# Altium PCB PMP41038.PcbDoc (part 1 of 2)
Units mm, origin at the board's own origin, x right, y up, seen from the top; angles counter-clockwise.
Board outline 101.5 x 48.5 mm, 4 copper layers (Top Layer, Signal Layer 1, Signal Layer 2, Bottom Layer), stack 0.713 mm thick; 126 components, 51 nets, 261 pads, 192 vias.
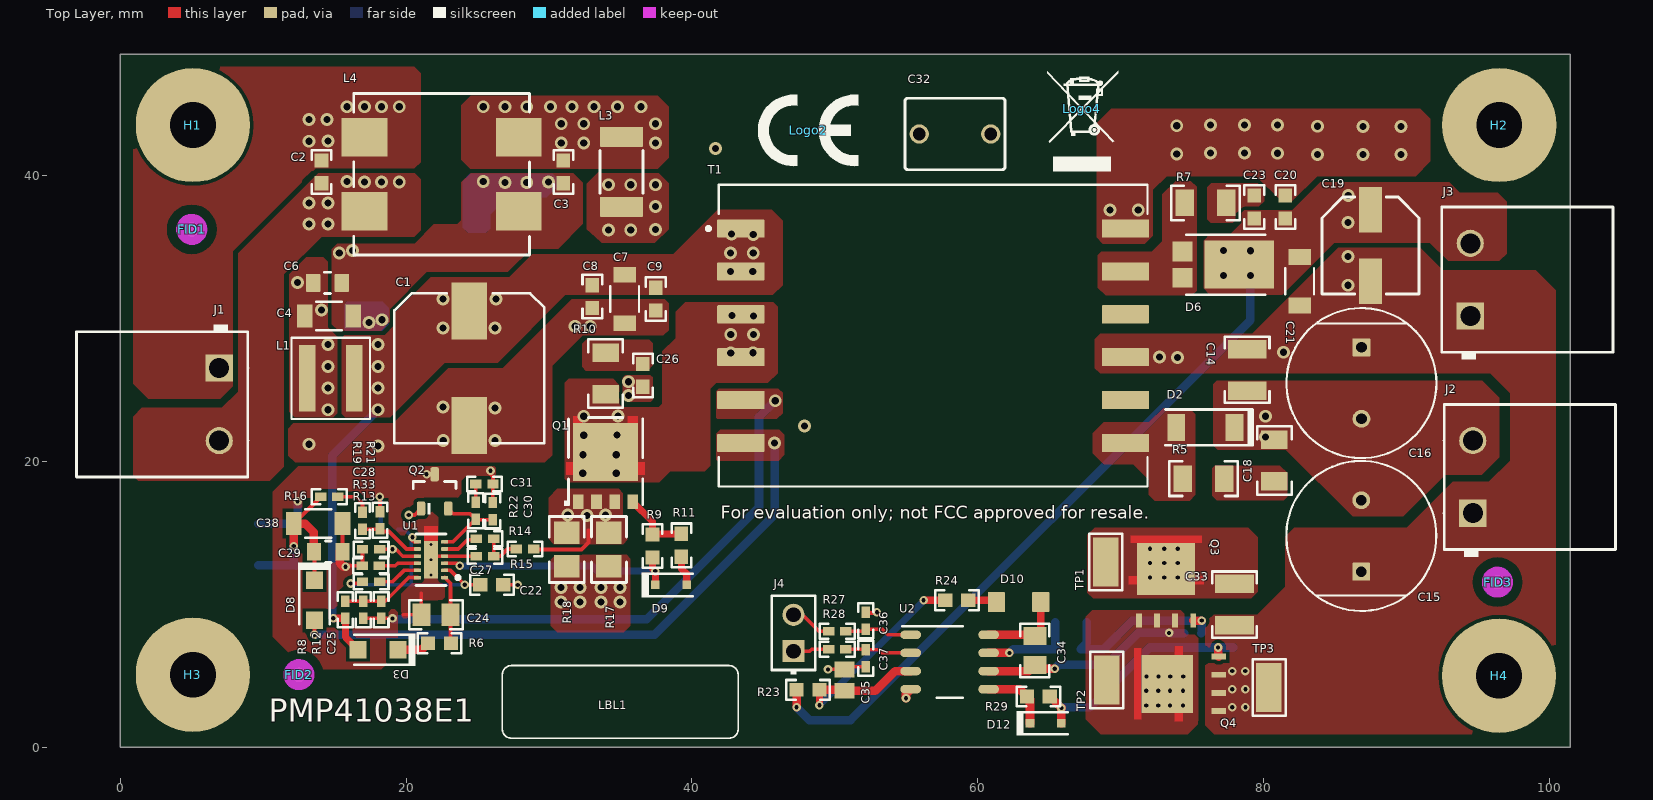
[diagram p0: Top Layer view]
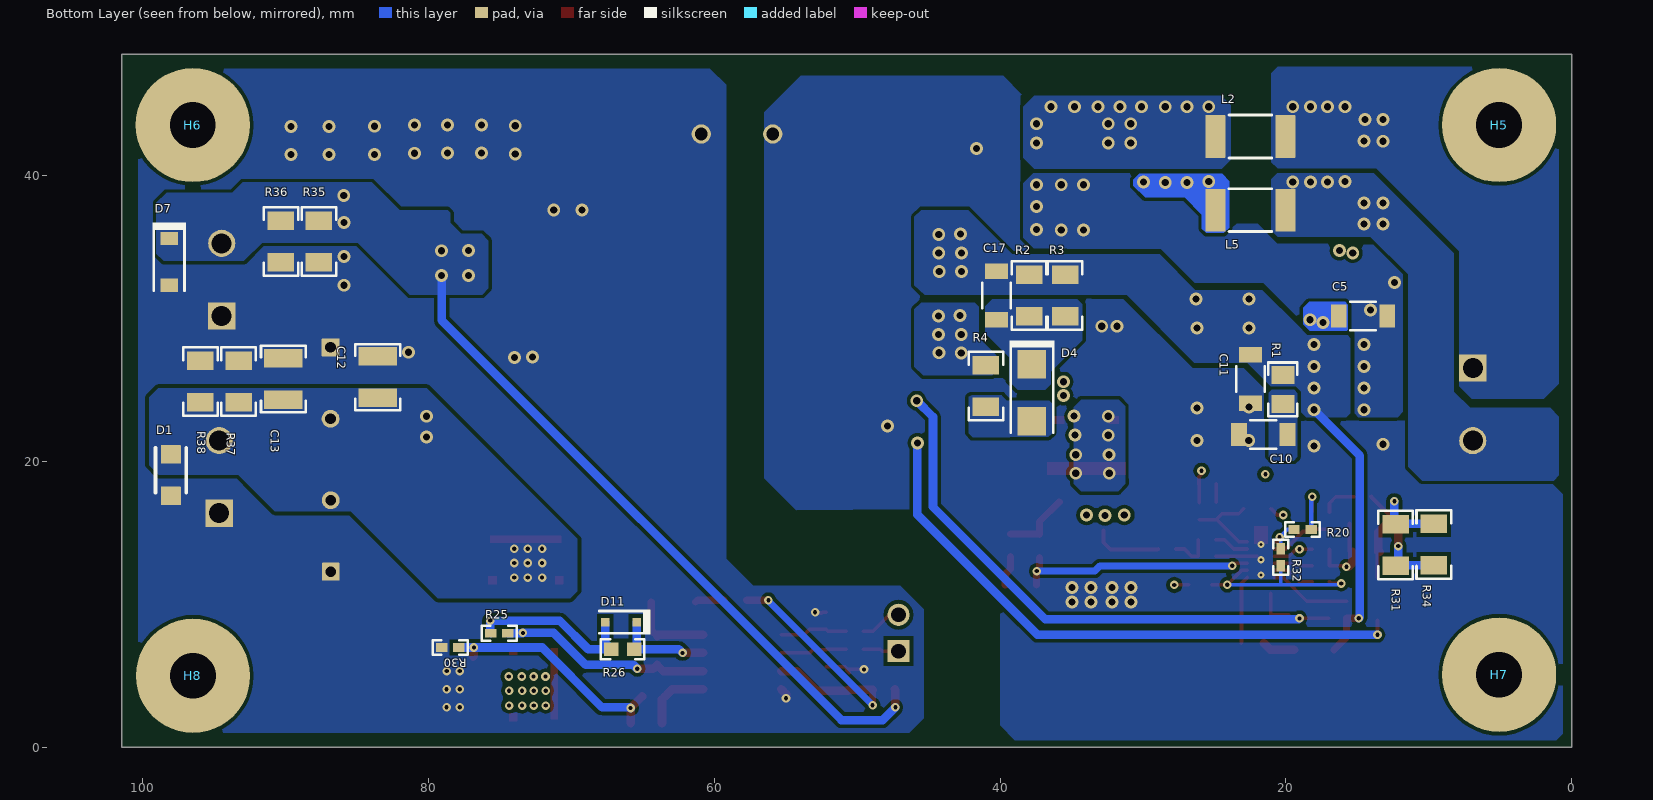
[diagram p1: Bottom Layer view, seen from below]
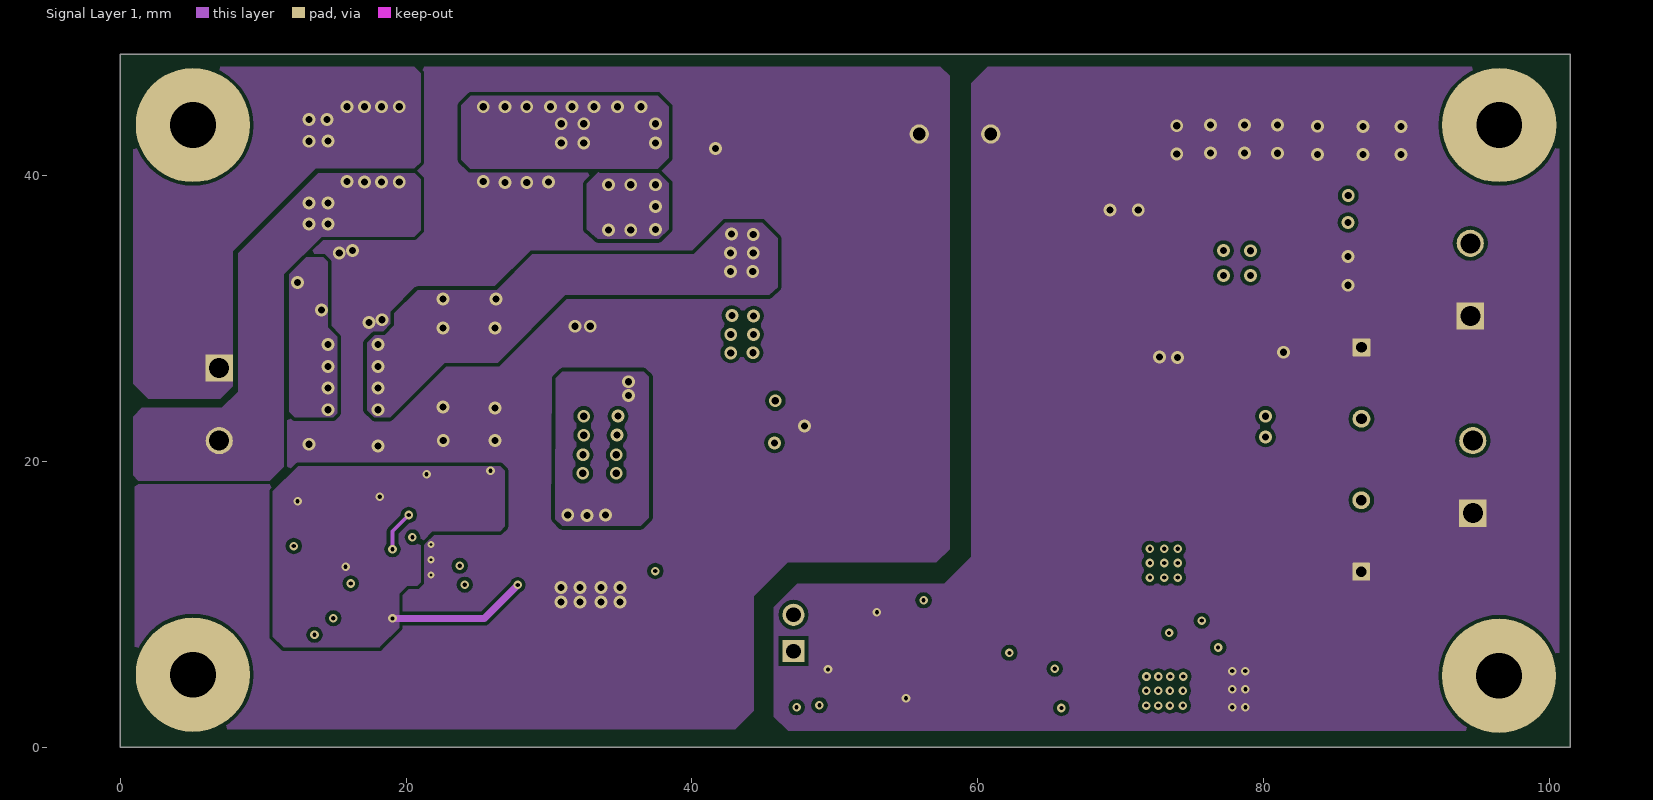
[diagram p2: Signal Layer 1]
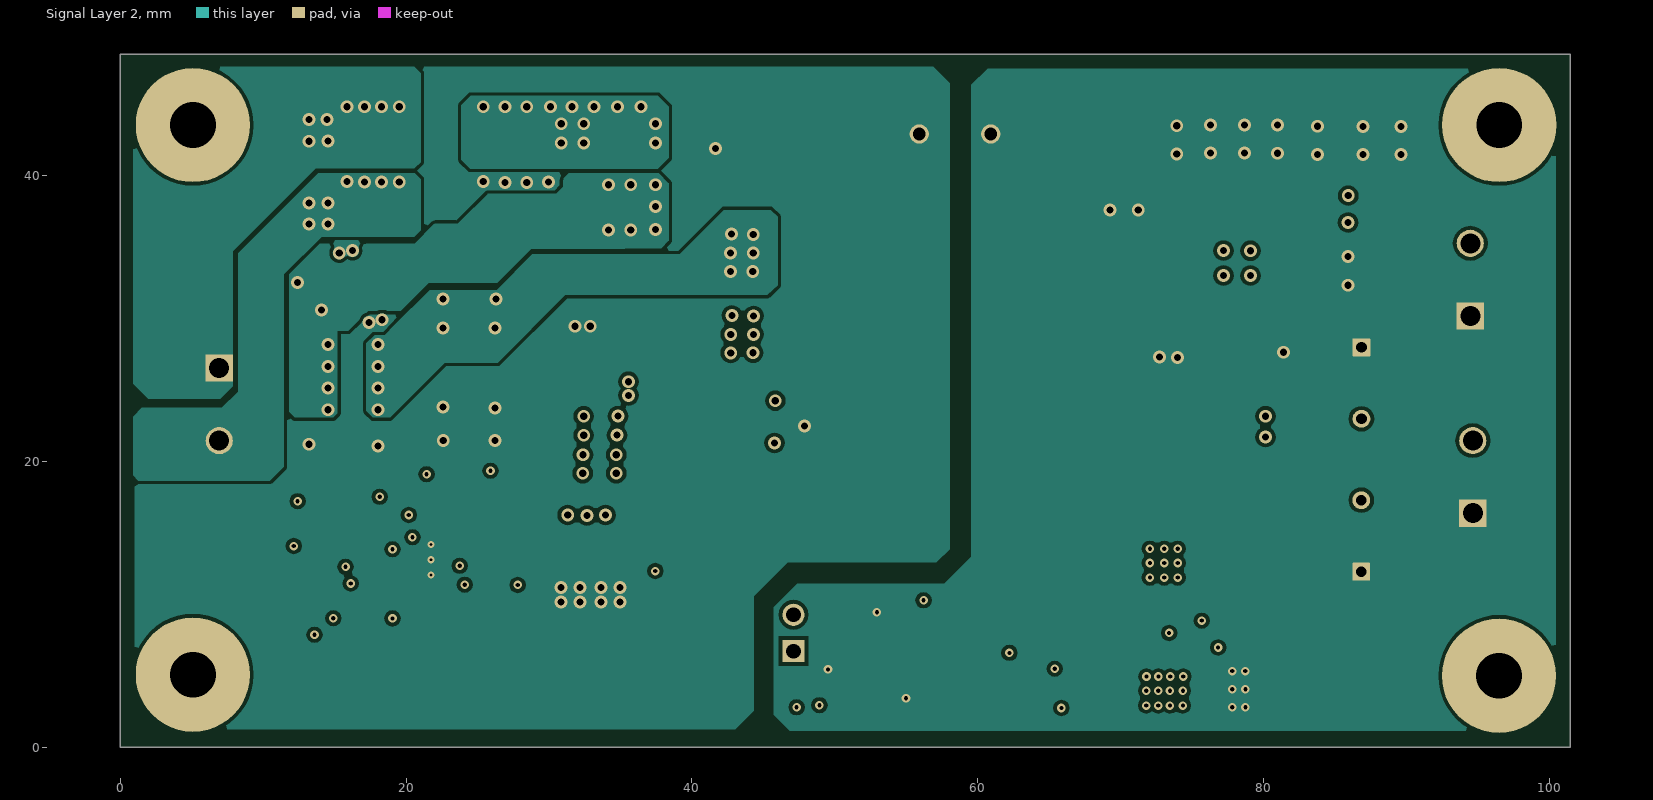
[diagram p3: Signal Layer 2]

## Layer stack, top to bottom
Top Solder: solder mask 0.0102, Solder Resist, Dk 3.5
Top Layer: signal copper 0.0356
Dielectric1: dielectric 0.19, Dk 4.2
Signal Layer 1: signal copper 0.036
Dielectric 4: dielectric 0.19, Dk 4.2
Signal Layer 2: signal copper 0.036
Dielectric 7: dielectric 0.19, Dk 4.2
Bottom Layer: signal copper 0.0356
Bottom Solder: solder mask 0.0102, Solder Resist, Dk 3.5

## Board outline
0,0 0,48.5 101.5,48.5 101.5,0

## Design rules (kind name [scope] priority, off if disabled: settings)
AcuteAngle [All] p1: minimum=4.50000000000000E+0001 checktracksonly=FALSE
AssemblyTestPointUsage [All] p1: valid=2
Clearance Clearance_BoardEdge_MountingHoles [OnCopper and InComponentClass('Mounting Holes') vs IsKeepOut] p1: gap=1.016 ignorepadtopadclearanceinfootprint=FALSE except(0: Arc-Hole Track-Hole SMDPad-Hole THPad-Hole Via-Hole Fill-Hole Poly-Hole Region-Hole Text-Hole)
Clearance Clearance_BoardEdge_Poly [OnCopper and InPoly vs IsKeepOut] p2: gap=0.635 ignorepadtopadclearanceinfootprint=FALSE except(0: Arc-Hole Track-Hole SMDPad-Hole THPad-Hole Via-Hole Fill-Hole Poly-Hole Region-Hole Text-Hole)
Clearance Clearance_BoardEdge [OnCopper and Not InComponentClass('Logo') and not InComponentClass('FiducialMark') and not InRegion(1000,500,4000,800) and Not IsKeepout vs IsKeepOut] p3: gap=0.127 ignorepadtopadclearanceinfootprint=FALSE except(0: Arc-Hole Track-Hole SMDPad-Hole THPad-Hole Via-Hole Fill-Hole Poly-Hole Region-Hole Text-Hole)
Clearance Clearance_Poly [InPolygon] p4: gap=0.254 ignorepadtopadclearanceinfootprint=FALSE except(0: Arc-Hole Track-Hole SMDPad-Hole THPad-Hole Via-Hole Fill-Hole Poly-Hole Region-Hole Text-Hole)
Clearance [All] p5: gap=0.203 ignorepadtopadclearanceinfootprint=FALSE except(0: Arc-Hole Track-Hole SMDPad-Hole THPad-Hole Via-Hole Fill-Hole Poly-Hole Region-Hole Text-Hole)
ComponentClearance ComponentClearance_Logo [All] p1: gap=0.254 collisioncheckmode=3 verticalgap=0.254 showdistances=TRUE
ComponentClearance ComponentClearance_ScrewToNut [(HasFootprint('NY PMS 440 0025 PH')) vs (HasFootprint('Keystone_1902C'))] p2: gap=0.127 collisioncheckmode=3 verticalgap=0.254 showdistances=FALSE
ComponentClearance ComponentClearance_MountingHoles [InComponentClass('Mounting Holes')] p3: gap=0.254 collisioncheckmode=3 verticalgap=2540 showdistances=FALSE
ComponentClearance ComponentClearance_SmallPassives [HasFootprint('0201*') or HasFootprint('0402*') or HasFootprint('0508') or HasFootprint('0603*') or HasFootprint('0612') or HasFootprint('0805*') or HasFootprint('0815*') or HasFootprint('0830*') or HasFootprint('1206*') or HasFootprint('1210*') or HasFootprint('1808*') or HasFootprint('1812*') or HasFootprint('1825*') or HasFootprint('2010*') or HasFootprint('2220*') or HasFootprint('2225*') or HasFootprint('2512*') or HasFootprint('2728*') or HasFootprint('3518*') vs HasFootprint('0201*') or HasFootprint('0402*') or HasFootprint('0508') or HasFootprint('0603*') or HasFootprint('0612') or HasFootprint('0805*') or HasFootprint('0815*') or HasFootprint('0830*') or HasFootprint('1206*') or HasFootprint('1210*') or HasFootprint('1808*') or HasFootprint('1812*') or HasFootprint('1825*') or HasFootprint('2010*') or HasFootprint('2220*') or HasFootprint('2225*') or HasFootprint('2512*') or HasFootprint('2728*') or HasFootprint('3518*')] p4: gap=0.254 collisioncheckmode=3 verticalgap=0.254 showdistances=FALSE
ComponentClearance ComponentClearance_THtoSMT [IsThruComponent vs IsSMTComponent] p5: gap=0.254 collisioncheckmode=3 verticalgap=2540 showdistances=FALSE
ComponentClearance ComponentClearance_THtoTH [IsThruComponent vs IsThruComponent] p6: gap=0.254 collisioncheckmode=3 verticalgap=2540 showdistances=FALSE
ComponentClearance [All] p7: gap=0.254 collisioncheckmode=3 verticalgap=0.254 showdistances=FALSE
DiffPairsRouting [All] p1: maxlimit=2.54 minlimit=0.254 mostfreqgap=0.254 toplayer_minwidth=0.381 toplayer_maxwidth=0.381 toplayer_prefwidth=0.381 midlayer1_minwidth=0.381 midlayer1_maxwidth=0.381 midlayer1_prefwidth=0.381 midlayer6_minwidth=0.381 midlayer6_maxwidth=0.381 midlayer6_prefwidth=0.381 bottomlayer_minwidth=0.381 bottomlayer_maxwidth=0.381 bottomlayer_prefwidth=0.381 maxuncoupledlength=25.4
FabricationTestPointUsage TestPointUsage [All] p1: valid=2 allowmultiple=FALSE
FabricationTestpoint Testpoint [All] p1: side=3 testpointundercomponent=TRUE minsize=1.016 maxsize=2.54 preferedsize=1.524 minholesize=0 maxholesize=1.016 preferedholesize=0.813 testpointgrid=0.025 allowsidetop=TRUE allowsidebottom=TRUE usegrid=TRUE gridtolerance=0
FanoutControl Fanout_LCC [IsLCC] p1: bgadir=Out bgaviamode=Centered fanoutstyle=Auto fanoutdirection=Alternating viagrid=0.025 // Fanout_LCC (Default Rule)
FanoutControl Fanout_BGA [IsBGA] p2: bgadir=Out bgaviamode=Centered fanoutstyle=Auto fanoutdirection=Alternating viagrid=0.025 // Fanout_BGA (Default Rule)
FanoutControl Fanout_Default [All] p4: bgadir=Out bgaviamode=Centered fanoutstyle=Auto fanoutdirection=Alternating viagrid=0.025 // Fanout_Default (Default Rule)
FanoutControl Fanout_Small [(CompPinCount < 5)] p5: bgadir=Out bgaviamode=Centered fanoutstyle=Auto fanoutdirection=OutThenIn viagrid=0.025 // Fanout_Small (Default Rule)
HoleSize [All] p1: absolutevalues=TRUE maxlimit=6.375 minlimit=0.152 maxpercent=80.000 minpercent=20.000
MinimumAnnularRing [All] p1: minimumring=0.076
MinimumSolderMaskSliver MinimumSolderMaskSliver_Logo [InComponentClass('Logo') vs InComponentClass('Logo')] p1: minsoldermaskwidth=0.018
MinimumSolderMaskSliver [All] p2: minsoldermaskwidth=0
PlaneConnect [All] p1: planeconnectstyle=Direct reliefexpansion=0.254 reliefentries=4 reliefconductorwidth=0.254 reliefairgap=0.254
PolygonConnect [All] p1: connectstyle=Direct reliefconductorwidth=0.254 reliefentries=4 polygonreliefangle="90 Angle" airgapwidth=0.254
RoutingCorners [All] p1: cornerstyle=45-Degree minsetback=0.254 maxsetback=2.54
RoutingLayers [All] p1: top layer_v5=TRUE mid layer 1_v5=TRUE mid layer 6_v5=FALSE bottom layer_v5=TRUE
RoutingVias [All] p1: holewidth=0.406 width=0.864 viastyle="Through Hole" minholewidth=0.203 minwidth=0.406 maxholewidth=1.016 maxwidth=1.651
SMDToCorner [All] p1: distance=0
SilkToBoardRegionClearance [Not ((IsComment or IsDesignator) And (Hide <> 'False')) and not InRegion(1000,500,4000,800)] p1:
SilkToSilkClearance [All] p1: silktosilkclearance=0
SilkToSolderMaskClearance SilkscreenOverComponentPads [IsPad] p1: minsilkscreentomaskgap=0 clearancetoexposedcopper=TRUE
SolderMaskExpansion [All] p1: expansion=0.076
Width [All] p1: maxlimit=2.54 minlimit=0.152 preferedwidth=0.254 checkconnectedcopper=TRUE
13 further rules are at their usual default settings.

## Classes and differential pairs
component class Header: J4
component class "PMP41038 Driver": C33 C34 C35 C36 C37 D10 D11 D12 J4 Q3 Q4 R23 R24 R25 R26 R27 R28 R29 R30 TP1 TP2 TP3 U2
component class "PMP41038 PowerSupply": C1 C2 C3 C4 C5 C6 C7 C8 C9 C10 C11 C12 C13 C14 C15 C16 C17 C18 C19 C20 C21 C22 C23 C24 C25 C26 C27 C28 C29 C30 C31 C32 C38 D1 D2 D3 D4 D6 D7 D8 D9 J1 J2 J3 L1 L2 L3 L4 L5 NT1 Q1 Q2 R1 R2 R3 R4 R5 R6 R7 R8 R9 R10 R11 R12 R13 R14 R15 R16 R17 R18 R19 R20 R21 R22 R31 R32 R33 R34 R35 R36 R37 R38 T1 U1
component class "Mounting Holes": H1 H2 H3 H4
component class Logo: Logo1
component class PMP41038_Hardware: FID1 FID2 FID3 H1 H2 H3 H4 H5 H6 H7 H8 LBL1 Logo1 Logo2 Logo3 Logo4 ZZ1 ZZ2 ZZ3 ZZ4
component class FiducialMark: FID1 FID2 FID3
component class AssemblyNote: ZZ1 ZZ2 ZZ3 ZZ4
component class Label: LBL1

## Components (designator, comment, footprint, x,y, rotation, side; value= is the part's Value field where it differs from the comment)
C1 "EEHZA1H101P" SM_RADIAL_10BMM 24.431,26.524 r270 top value=100uF
C2 "CGA3E2X7R1H104K080AA" 0603 14.082,40.275 r270 top value=0.1uF
C3 "CGA3E2X7R1H104K080AA" 0603 31.012,40.275 r270 top value=0.1uF
C4 "CGA5L1X7R1H106K160AC" 1206_190 14.606,30.188 r0 top value=10uF
C5 "CGA5L1X7R1H106K160AC" 1206_190 14.606,30.188 r0 bottom value=10uF
C6 "CGA4J3X7R1H105K125AB" 0805_HV1 14.5,32.503 r0 top value=1uF
C7 "CGA5L1X7R1H106K160AC" 1206_190 35.306,31.374 r270 top value=10uF
C8 "CGA3E2X7R1H104K080AA" 0603 33.041,31.545 r270 top value=0.1uF
C9 "CGA3E2X7R1H104K080AA" 0603 37.48,31.371 r270 top value=0.1uF
C10 "CGA5L1X7R1H106K160AC" 1206_190 21.59,21.897 r0 bottom value=10uF
C11 "CGA5L1X7R1H106K160AC" 1206_190 22.479,25.781 r270 bottom value=10uF
C12 "GRM32DR72E224KW01L" 1210_220 83.566,25.908 r270 bottom value=0.22uF
C13 "GRM32DR72E224KW01L" 1210_220 90.17,25.781 r270 bottom value=0.22uF
C14 "GRM32DR72E224KW01L" 1210_220 78.867,26.416 r270 top value=0.22uF
C15 "UVK2D220MPD" FP-UVK2D220MPD_RADIAL-MFG 86.859,14.792 r90 top value=22µF
C16 "UVK2D220MPD" FP-UVK2D220MPD_RADIAL-MFG 86.868,25.49 r270 top value=22µF
C17 "CGA5L2X7R2A104K160AA" 1206_180 40.259,31.623 r270 bottom value=0.1uF
C18 "GRM31A5C2J101JW01D" 1206 80.772,20.066 r270 top value=100pF
C19 "EEH-ZA1E101XP" Panasonic_D8 87.503,35.114 r270 top value=100uF
C20 "CGA3E2X7R1H104K080AA" 0603 81.55,37.813 r270 top value=0.1uF
C21 "CGA5L1X7R1E106K160AE" 1206_190 82.55,32.614 r270 top value=10uF
C22 "GCM188R71E105KA64D" 0603 26,11.379 r0 top value=1uF
C23 "GRM1885C2A681JA01D" 0603 79.375,37.813 r90 top value=680pF
C24 "CGA4J3X7R1H105K125AB" 0805_HV 22.09,9.279 r180 top value=1uF
C25 "CGA2B2X7R1H221K050BA" 0402 18.25,9.629 r270 top value=220pF
C26 "GCM1885C2A102JA16D" 0603 36.576,26.03 r270 top value=1000pF
C27 "GCM155R71H102KA37D" 0402 25.525,13.379 r180 top value=1000pF
C28 "GCM155R71C104JA55D" 0402 17.55,13.859 r180 top value=0.1uF
C29 "CGA4J3X7R1H105K125AB" 0805_HV1 14.55,13.684 r0 top value=1uF
C30 "GCM155R71H102KA37D" 0402 26.075,16.532 r90 top value=1000pF
C31 "CGA2B3X7R1H683K050BB" 0402 25.486,18.429 r0 top value=0.068uF
C32 "CS95ZU2GA332MAGKA" CK45-RR_700x500x1100 58.42,42.926 r180 top value=3300pF
C33 "GRM32DR72E224KW01L" 1210_220 77.983,9.988 r270 top value=0.22uF
C34 "GCM21BR71H474KA55L" 0805_HV 64.016,6.773 r270 top value=0.47uF
C35 "CGA4J1X7R1E475K125AC" 0805L 50.673,4.699 r90 top value=4.7uF
C36 "CGA2B2C0G1H101J050BA" 0402 52.184,8.848 r90 top value=100pF
C37 "CGA2B2C0G1H101J050BA" 0402 52.184,6.223 r270 top value=100pF
C38 "CGA5L1X7R1H106K160AC" 1206_190 13.848,15.658 r0 top value=10uF
D1 "BZD27C200P-E3-08" DO-219AB 98.044,19.05 r270 bottom value=200V
D2 "ES1JAF" SMAF 75.946,22.393 r180 top value=600V
D3 "PMEG10010ELRX" SOD-123W 18.034,6.823 r180 top value=100V
D4 "ES1D-E3/61T" SMA 37.786,24.822 r270 bottom value=200V
D6 "PDS3100Q-13" POWERDI5 76.327,33.782 r0 top value=100V
D7 "BZT52C18-7-F" SOD-123 98.171,33.974 r270 bottom value=18V
D8 "PMEG10010ELRX" SOD-123W 13.589,10.287 r270 top value=100V
D9 "BAT54WSQ-7-F" SOD-323 38.549,11.361 r0 top value=30V
D10 "US1DFA" SOD-123FA 62.873,10.16 r180 top value=200V
D11 "BAT54WSQ-7-F" SOD-323 66.548,8.763 r0 bottom value=30V
D12 "BAT54WSQ-7-F" SOD-323 64.77,1.691 r0 top value=30V
FID1 "Fiducial" Fiducial10-20 5,36.25 r0 top
FID2 "Fiducial" Fiducial10-20 12.5,5.08 r0 top
FID3 "Fiducial" Fiducial10-20 96.393,11.557 r0 top
H1 "NY PMS 440 0025 PH" "NY PMS 440 0025 PH" 5.08,43.55 r0 top
H2 "NY PMS 440 0025 PH" "NY PMS 440 0025 PH" 96.513,43.55 r0 top
H3 "NY PMS 440 0025 PH" "NY PMS 440 0025 PH" 5.08,5.08 r0 top locked
H4 "NY PMS 440 0025 PH" "NY PMS 440 0025 PH" 96.5,5 r0 top
H5 "1902C" Keystone_1902C 5.08,43.55 r180 bottom
H6 "1902C" Keystone_1902C 96.513,43.55 r180 bottom
H7 "1902C" Keystone_1902C 5.08,5.08 r180 bottom locked
H8 "1902C" Keystone_1902C 96.5,5 r180 bottom
J1 "1759017" Phoenix_1759017 6.923,24 r270 top
J2 "1759017" Phoenix_1759017 94.661,18.923 r90 top
J3 "1759017" Phoenix_1759017 94.488,32.733 r90 top
J4 "PEC01DAAN" Sullins_PxC01DAAN 47.117,8.001 r90 top
L1 "XAL5030-472MEB" XAL5030 14.732,25.815 r0 top value=4.7uH
L2 "74279226101" 1812_170_HighSpeed 22.49,42.75 r0 bottom value="100 ohm"
L3 "74279226101" 1812_170_HighSpeed 35.075,40.277 r270 top value="100 ohm"
L4 "ACM1211-701-2PL-TL01" TDK_ACM1211 22.49,40.108 r90 top
L5 "74279226101" 1812_170_HighSpeed 22.49,37.592 r0 bottom value="100 ohm"
LBL1 "THT-14-423-10" Label_650x200 34.991,3.175 r0 top
Logo1 "Texas Instruments" TI_Stacked_Overlay_Small 126.619,17.526 r0 top
Logo2 "CE Mark" CE_Mark_5mm 48.133,43.18 r0 top
Logo3 "FCC disclaimer" FCC_disclaimer 59.69,65.852 r0 top
Logo4 "WEEE logo" WEEE_Minimum 67.31,44.698 r0 top
Q1 "NVMFS5C670NLWFAFT1G" SO-8FL 33.962,19.973 r90 top value=60V
Q2 "MMBT3906" SOT-23 22,17.907 r90 top value="40 V"
Q3 "SQJ454EP-T1_GE3" PowerPAK_SO-8L 73.197,11.685 r90 top value=200V
Q4 "SQJ454EP-T1_GE3" PowerPAK_SO-8L 74.083,4.445 r180 top value=200V
R1 "RC0805JR-071RL" 0805_HV 20.21,25.053 r90 bottom value=1.0
R2 "CRCW120656K0JNEA" 1206 37.971,31.623 r90 bottom value=56k
R3 "CRCW120656K0JNEA" 1206 35.459,31.623 r90 bottom value=56k
R4 "CRCW120610R0JNEA" 1206 40.999,25.279 r90 bottom value=10
R5 "CRCW120630R0JNEA" 1206 75.819,18.796 r0 top value=DNP
R6 "CRCW060310R0FKEA" 0603 22.34,7.279 r180 top value=10.0
R7 "CRCW120630R0JNEA" 1206 75.946,38.1 r0 top value=DNP
R8 "CRCW040266K5FKED" 0402 15.75,9.629 r270 top value=66.5k
R9 "CRCW060310R0FKEA" 0603 37.25,14.089 r90 top value=10.0
R10 "CRCW120620R0JNEA" 1206 33.962,26.162 r270 top value=20
R11 "CRCW06030000Z0EA" 0603 39.274,14.139 r270 top value=0
R12 "CRCW040215K4FKED" 0402 17,9.629 r90 top value=15.4k
R13 "CRCW0402100KJNED" 0402 17.55,11.579 r180 top value=100k
R14 "ERJ-2GEJ102X" 0402 25.527,14.605 r180 top value=1.0k
R15 "CRCW0402100RFKED" 0402 28.324,13.879 r0 top value=100
R16 "CRCW0402100RFKED" 0402 14.628,17.526 r180 top value=100
R17 "PE1206FRF470R007L" PE1206 34.195,13.843 r90 top value=0.007
R18 "PE1206FRF470R007L" PE1206 31.242,13.843 r90 top value=0.007
R19 "CRCW04023K92FKED" 0402 16.95,15.857 r90 top value=3.92k
R20 "CRCW04020000Z0ED" 0402 18.836,15.24 r180 bottom value=0
R21 "ERJ-2GEJ102X" 0402 18.173,15.89 r270 top value=1.0k
R22 "CRCW04022K70JNED" 0402 24.866,16.554 r270 top value=2.7k
R23 "CRCW060310R0FKEAHP" 0603 48.133,4.017 r180 top value=10.0
R24 "CRCW06033R30JNEA" 0603 58.547,10.287 r0 top value=3.3
R25 "RMCF0402FT10K0" 0402 75.057,7.988 r0 bottom value=10.0k
R26 "CRCW060310R0FKEAHP" 0603 66.421,6.858 r0 bottom value=10.0
R27 "CRCW040210R0FKED" 0402 50.173,8.128 r0 top value=10.0
R28 "CRCW040210R0FKED" 0402 50.173,6.858 r0 top value=10.0
R29 "CRCW060310R0FKEAHP" 0603 64.262,3.556 r0 top value=10.0
R30 "RMCF0402FT10K0" 0402 78.486,6.985 r180 bottom value=10.0k
R31 "RC1206FR-07300RL" 1206 12.319,14.16 r270 bottom value=300
R32 "CRCW04020000Z0ED" 0402 20.372,13.294 r270 bottom value=DNP
R33 "CRCW040271K5FKED" 0402 17.526,12.7 r0 top value=71.5k
R34 "RC1206FR-07300RL" 1206 9.652,14.187 r270 bottom value=300
R35 "RP73D2B1K0BTG" 1206 87.684,35.412 r90 bottom value=1.00k
R36 "RP73D2B1K0BTG" 1206 90.351,35.412 r90 bottom value=1.00k
R37 "CRCW1206200KFKEA" 1206 93.309,25.601 r270 bottom value=200k
R38 "CRCW1206200KFKEA" 1206 95.976,25.601 r270 bottom value=200k
T1 "ZB1399-BL" FP-ZB1399-BL_SMT_TRANSFORMER_30MM00_21MM13-MFG 56.89,28.805 r0 top
TP1 "5015" Testpoint_Keystone_Miniature 68.961,12.961 r90 top
TP2 "5015" Testpoint_Keystone_Miniature 69.036,4.699 r90 top
TP3 "5015" Testpoint_Keystone_Miniature 80.391,4.191 r90 top
U1 "LM51561QDSSRQ1" DSS0012C-MFG 21.75,13.129 r180 top
U2 "UCC27712QDRQ1" D0008A_N 58.047,5.969 r0 top
ZZ1 "This Assembly Note is for PCB labels only" AssemblyNoteLabel 4.699,100.025 r0 top
ZZ2 "These assemblies are ESD sensitive, ESD precautions shall be observed." AssemblyNote 4.699,97.259 r0 top
ZZ3 "These assemblies must be clean and free from flux and all contaminants. Use of no clean flux is not acceptable." AssemblyNote 4.699,95.01 r0 top
ZZ4 "These assemblies must comply with workmanship standards IPC-A-610 Class 2, unless otherwise specified." AssemblyNote 4.699,92.761 r0 top

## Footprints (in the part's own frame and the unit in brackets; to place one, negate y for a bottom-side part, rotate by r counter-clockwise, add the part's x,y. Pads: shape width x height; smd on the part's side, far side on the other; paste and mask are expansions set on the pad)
0402 [mm] "0402 from SM-752 data"
  rect 0.8x0.6 smd: 1(-0.6,0) 2(0.6,0)
  silkscreen extent -1.22,-0.52 1.22,0.52, body extent -0.55,-0.3 0.55,0.3, height 0.6
0603 [mm] "0603 from SM-752 data"
  rect 1x0.95 smd: 1(-0.8,0) 2(0.8,0)
  silkscreen extent -1.52,-0.69 1.52,0.69, body extent -0.87,-0.47 0.87,0.47, height 1
0805_HV [mil] "0805 with 30mil clearance between pads"
  rect 50x63 smd: 1(-40,0) 2(40,0)
  silkscreen extent -74,-40 74,40, body extent -43,-29 43,29, height 57
0805_HV1 [mm] "Custom footprint based on analyzing multiple manufacturer recommendations"
  rrect10% 1x1.25 smd: 1(-1,0) 2(1,0)
  silkscreen extent -0.2,-0.75 0.2,0.75, body extent -1.1,-0.72 1.1,0.73, height 1.45
0805L [mm] "0805 from SM-752 data"
  rect 1.1x1.4 smd: 1(-0.75,0) 2(0.75,0)
  body extent -1.1,-0.72 1.1,0.72, height 1.45
1206 [mm] "1206 from SM-752 data"
  rect 1.3x1.85 smd: 1(-1.45,0) 2(1.45,0)
  silkscreen extent -2.4,-1.21 2.4,1.21, body extent -1.7,-0.9 1.7,0.9, height 1.35
1206_180 [mm] "1206_180"
  rect 1.1x1.6 smd: 1(-1.7,0) 2(1.7,0)
  silkscreen extent -0.9,-1 0.9,1, body extent -1.75,-0.95 1.75,0.95, height 1.8
1206_190 [mm] "1206_190"
  rect 1.1x1.6 smd: 1(-1.7,0) 2(1.7,0)
  silkscreen extent -0.9,-1 0.9,1, body extent -1.75,-0.95 1.75,0.95, height 1.9
1210_220 [mm] "1210"
  rect 1.3x2.7 smd: 1(-1.45,0) 2(1.45,0)
  silkscreen extent -2.32,-1.57 2.32,1.57, body extent -1.7,-1.35 1.7,1.35, height 2.2
1812_170_HighSpeed [mm] "Wurth recommended land pattern"
  rrect7% 1.4x3 smd: 1(-2.45,0) 2(2.45,0)
  silkscreen extent -1.5,-1.5 1.5,1.5, body extent -2.25,-1.6 2.25,1.6, height 1.51
AssemblyNote [mm] "Assembly Note"
AssemblyNoteLabel [mm] "Assembly Note for PCB Labels"
CE_Mark_5mm [mm] "Minimum text height for CE Mark"
  silkscreen extent -3.5,-2.5 3.5,2.5
CK45-RR_700x500x1100 [mm] "TH, 2-Leads, Body 7x5mm"
  round 1.35 hole 0.9: 1(-2.5,0) 2(2.5,0)
  silkscreen extent -3.5,-2.5 3.5,2.5, body extent -3.88,-2.5 3.88,2.5, height 11
D0008A_N [mm] "SOIC, 8-Leads, Body 4.9x3.9mm, Pitch 1.27mm, IPC Medium Density"
  oval 1.45x0.6 smd: 1(-2.725,1.905) 2(-2.725,0.635) 3(-2.725,-0.635) 4(-2.725,-1.905) 5(2.725,-1.905) 6(2.725,-0.635) 7(2.725,0.635) 8(2.725,1.905)
  silkscreen extent -3.3,-2.5 0.9,2.5, body extent -3,-2.45 3,2.45, height 1.63
DO-219AB [mm] "Vishay Semiconductor"
  rrect8% 1.3x1.4 smd: 1(-1.45,0) 2(1.45,0)
  silkscreen extent -1.9,-1.07 1.23,1.07, body extent -1.95,-0.95 1.95,0.95, height 1.09
DSS0012C-MFG [mm]
  rrect40% 0.5x0.25 smd paste+0 mask+0: 1(-0.95,1.25) 2(-0.95,0.75) 3(-0.95,0.25) 4(-0.95,-0.25) 5(-0.95,-0.75) 6(-0.95,-1.25) 7(0.95,-1.25) 8(0.95,-0.75) 9(0.95,-0.25) 10(0.95,0.25) 11(0.95,0.75) 12(0.95,1.25)
  rrect10% 1x2.65 smd paste-1000 mask+0: 13(0,0)
  silkscreen extent -2,-1.8 1.05,1.8, body extent -1.3,-1.65 1.3,1.65, height 0.25
FCC_disclaimer [mm]
Fiducial10-20 [mm]
  round 1 smd mask+0.5: 1(0,0)
  Top Layer keep-out circle w1.178: c0,0 r0.5
FP-UVK2D220MPD_RADIAL-MFG [mm]
  rrect8% 1.25x1.25 hole 0.75 paste-1000 mask+0: 1(-2.5,0)
  round 1.25 hole 0.75 paste-1000 mask+0: 2(2.5,0)
  silkscreen extent -5.25,-5.25 5.25,5.25, body extent -5.35,-5.35 5.35,5.35, height 0.25
FP-ZB1399-BL_SMT_TRANSFORMER_30MM00_21MM13-MFG [mm]
  rrect8% 3.3x1.27 smd paste+0 mask+0: 1(-13.46,7.5) 2(-13.46,4.5) 3(-13.46,1.5) 4(-13.46,-1.5) 5(-13.46,-4.5) 6(-13.46,-7.5) 7(13.46,-7.5) 8(13.46,-4.5) 9(13.46,-1.5) 10(13.46,1.5) 11(13.46,4.5) 12(13.46,7.5)
  silkscreen extent -15.85,-10.57 15,10.57, body extent -15.21,-10.67 15.21,10.67, height 0.25
Keystone_1902C [mil] "Hex Standoff, 4-40 threaded, nylon"
  round 1 on Mech4: 0(0,0)
  body extent -145,-126 146,126, height 501
Label_650x200 [mil] "Thermal Transfer Label"
  round 1 on Mech13: 0(0,0)
  silkscreen extent -325,-100 325,100, body extent -325,-100 325,100, height 1
"NY PMS 440 0025 PH" [mm] "4-40 nylon screw and mounting hole"
  round 8 hole 3.2: 1(0,0)
  body extent -3.3,-3.3 3.3,3.3, height 2.69
Panasonic_D8 [mm] "SMD, 2-Leads, Dia 6.3mm"
  rect 3.2x1.6 smd: 1(-2.5,0) 2(2.5,0)
  silkscreen extent -3.4,-3.4 3.4,3.4, body extent -3.4,-3.4 3.4,3.4, height 8.01
PE1206 [mm] "YAGEO"
  rect 1.57x1.78 smd: 1(-1.165,0) 2(1.165,0)
  silkscreen extent -2.3,-1.22 2.3,1.22, body extent -1.72,-0.92 1.72,0.92, height 0.89
Phoenix_1759017 [mm] "Header (Shrouded), 5.08mm, 2x1, R/A, TH"
  rect 1.9x1.9 hole 1.4: 1(-2.54,0)
  round 1.9 hole 1.4: 2(2.54,0)
  silkscreen extent -5.6,-10 5.08,2, body extent -5.08,-10 5.08,2, height 8.6
POWERDI5 [mm] "Diodes Inc recommended land pattern, ap02001.pdf rev 60"
  rect 1.4x1.39 smd: 1(-1.991,0.92) 2(-1.991,-0.92)
  rect 4.86x3.36 smd: 3(1.991,0)
  silkscreen extent -1.7,-2.1 3.8,2.1, body extent -2.27,-2.03 4.33,2.03, height 1.17
PowerPAK_SO-8L [mm] "based on Vishay recommended land pattern Document 63818 Feb 7, 2012"
  rect 1x0.41 smd: 1(-2.805,1.905) 2(-2.805,0.635) 3(-2.805,-0.635) 4(-2.805,-1.905)
  rect 3.63x4.061 smd: 5(0.805,0)
  Top Layer region: 2.615,-2.5 3.125,-2.5 3.125,2.5 2.615,2.5
  Top Layer region: -0.298,2.03 0.297,2.03 0.297,2.64 -0.298,2.64
  Top Layer region: -0.297,-2.64 0.298,-2.64 0.298,-2.03 -0.297,-2.03
  body extent -3.07,-2.57 3.08,2.57, height 1.21
SM_RADIAL_10BMM [mm] "Nichicon 10x10"
  rect 4x2.5 smd: 1(-4,0) 2(4,0)
  silkscreen extent -5.25,-5.25 5.25,5.25, body extent -5.25,-5.25 5.25,5.25, height 10.5
SMA [mm] "Molded Diode, 2-Leads, Body 4.3x2.6mm, IPC Medium Density, based on OnSemi component dimensions and land pattern"
  rect 2x2 smd: 1(-2,0) 2(2,0)
  silkscreen extent -3.66,-1.57 2.79,1.57, body extent -2.6,-1.3 2.6,1.3, height 2.42
SMAF [mm] "SMD, 2-Leads, Body 3.8x2.5mm"
  rect 1.24x1.89 smd: 1(-2.04,0) 2(2.04,0)
  silkscreen extent -3.4,-1.3 2.8,1.3, body extent -2.35,-1.25 2.35,1.25, height 1
SO-8FL [mm] "ON SEMICONDUCTOR, DFN5 5x6, 1.27P, CASE 488AA"
  rect 1x0.75 smd: 1(-2.795,1.905) 2(-2.795,0.635) 3(-2.795,-0.635) 4(-2.795,-1.905)
  rect 4.055x4.56 smd: 5(0.698,0)
  Top Layer region: 3.2,-2.28 3.2,-1.53 2.65,-1.53 2.65,-2.28
  Top Layer region: 3.2,1.53 3.2,2.28 2.655,2.28 2.655,1.53
  Top Layer region: 0,-2.775 0,2.775 -0.905,2.775 -0.905,-2.775
  silkscreen extent -3.1,-2.6 3.1,2.9, body extent -3.17,-2.67 3.17,2.67, height 1.11
SOD-123 [mm] "On Semi recommended land pattern"
  rect 0.915x1.22 smd: 1(-1.637,0) 2(1.637,0)
  silkscreen extent -2.74,-1.17 2.03,1.17, body extent -1.93,-0.9 1.93,0.9, height 1.35
SOD-123FA [mm] "SMD, 2-Leads, Body 2.8x1.8mm"
  rrect8% 1.2x1.4 smd paste-0.05: 1(-1.55,0) 2(1.55,0)
  body extent -1.9,-0.95 1.9,0.95, height 1.43
SOD-123W [mm] "NXP recommended land pattern"
  rect 1.2x1.2 smd paste-0.05: 1(-1.4,0) 2(1.4,0)
  silkscreen extent -2.64,-1.14 1.68,1.14, body extent -1.85,-0.95 1.85,0.95, height 1.1
SOD-323 [mm] "NXP recommended land pattern"
  rect 0.6x0.6 smd paste-0.05: 1(-1.1,0) 2(1.1,0)
  silkscreen extent -2.06,-0.86 1.53,0.86, body extent -1.3,-0.67 1.3,0.68, height 1.1
SOT-23 [mm] "SOT23, 3-Leads, Body 2.9x1.3mm, Pitch 0.95mm, Lead Span 2.5mm, IPC Medium Density"
  rrect50% 1x0.6 smd: 1(-1.2,0.95) 2(-1.2,-0.95) 3(1.2,0)
  silkscreen extent -1.62,-1.5 0.7,1.5, body extent -1.16,-1.45 1.21,1.45, height 1
Sullins_PxC01DAAN [mm] "Header, 2.54mm, 1x2, TH"
  rect 1.55x1.55 hole 1.016: 1(-1.27,0)
  round 1.55 hole 1.016: 2(1.27,0)
  silkscreen extent -2.9,-1.53 2.61,1.53, body extent -2.61,-1.53 2.61,1.53, height 8.71
TDK_ACM1211 [mm] "SMT, 4-Leads, Body 12x11mm"
  rect 2.7x3.2 smd: 1(-2.6,5.4) 2(2.6,5.4) 3(2.6,-5.4) 4(-2.6,-5.4)
  silkscreen extent -5.65,-6.15 5.65,6.15, body extent -5.65,-6.15 5.65,6.15, height 6
Testpoint_Keystone_Miniature [mil] "Miniature SMT test point"
  rect 135x70 smd: 1(0,0)
  silkscreen extent -78,-46 78,45, body extent -52,-20 52,20, height 61
TI_Stacked_Overlay_Small [mm]
  silkscreen extent -10.63,-2.49 10.63,2.49
WEEE_Minimum [mm] "WEEElie bin"
  silkscreen extent -2.42,-4.38 2.52,2.65
XAL5030 [mil] "Coilcraft XAL5030 12/12/11"
  rect 46x183 smd: 1(-65,0) 2(65,0)
  silkscreen extent -108,-112 108,112, body extent -108,-112 108,112, height 122

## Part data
C1: library part CMP-0012576-3, "CAP, Polymer Hybrid, 100 uF, 50 V, +/- 20%, 28 ohm, 10x10 SMD", Manufacturer=Panasonic, Supplier Part Number 1=P15442CT-ND, Tolerance_%=20%, Value1="28 ohm", Value2=50V, ValueDisplayed=100uF
C2 C3 C8 C9 C20: library part CMP-0007078-2, "CAP, CERM, 0.1 uF, 50 V, +/- 10%, X7R, AEC-Q200 Grade 1, 0603", Cap_Case=0603, Manufacturer=TDK, Supplier Part Number 1=445-5666-1-ND, Tempco=X7R, Tolerance_%=10%, Value1="0.0296 ohm", Value2=50V, ValueDisplayed=0.1uF
C4 C5 C7 C10 C11 C38: library part CMP-0085950-1, "CAP, CERM, 10 µF, 50 V,+/- 10%, X7R, AEC-Q200 Grade 1, 1206", Cap_Case=1206, Manufacturer=TDK, Tempco=X7R, Tolerance_%=10%, Value2=50V, ValueDisplayed=10µF
C6 C29: library part CMP-0007976-1, "CAP, CERM, 1 uF, 50 V, +/- 10%, X7R, AEC-Q200 Grade 1, 0805", Cap_Case=0805, Manufacturer=TDK, Supplier Part Number 1=445-6961-1-ND, Tempco=X7R, Tolerance_%=10%, Value1="0.008782 ohm", Value2=50V, ValueDisplayed=1uF
C12 C13 C14 C33: library part CMP-0009193-2, "CAP, CERM, 0.22 uF, 250 V, +/- 10%, X7R, 1210", Cap_Case=1210, Manufacturer=MuRata, Supplier Part Number 1=490-3545-1-ND, Tempco=X7R, Tolerance_%=10%, Value1=Unknown, Value2=250V, ValueDisplayed=0.22uF
C15 C16: library part CMP-0096325-1, "22 µF 200 V Aluminum Electrolytic Capacitors Radial, Can 2000 Hrs @ 85°C", Digikey Part Number=UVK2D220MPD-ND, Leakage Current=276uA, Manufacturer=Nichicon, Mouser Part Number=647-UVK2D220MPD, Operating Temperature Range="-40°C to +85°C", Tolerance_%=20%, ValueDisplayed=22uF
C17: library part CMP-0008778-1, "CAP, CERM, 0.1 uF, 100 V, +/- 10%, X7R, AEC-Q200 Grade 1, 1206", Cap_Case=1206_180, Manufacturer=TDK, Supplier Part Number 1=445-5840-1-ND, Tempco=X7R, Tolerance_%=10%, Value1="0.030343 ohm", Value2=100V, ValueDisplayed=0.1uF
C18: library part CMP-0008884-2, "CAP, CERM, 100 pF, 630 V, +/- 5%, C0G/NP0, 1206", Cap_Case=1206, Manufacturer=MuRata, Supplier Part Number 1=490-5273-1-ND, Tempco=C0G/NP0, Tolerance_%=5%, Value1=Unknown, Value2=630V, ValueDisplayed=100pF
C19: library part CMP-0860234-1, "CAP, Aluminum Polymer, 100 µF, 25 V,+/- 20%, 0.03 ohm, AEC-Q200 Grade 2, D6.3xL7.7mm SMD", Cap_Case=6.3x7.7mm, Manufacturer=Panasonic, Tolerance_%=20%, Value1="0.03 ohm", Value2=25V, ValueDisplayed=100µF
C21: library part CMP-0085253-1, "CAP, CERM, 10 µF, 25 V,+/- 10%, X7R, AEC-Q200 Grade 1, 1206", Cap_Case=1206, Manufacturer=TDK, Tempco=X7R, Tolerance_%=10%, Value2=25V, ValueDisplayed=10µF
C22: library part CMP-0007139-1, "CAP, CERM, 1 uF, 25 V, +/- 10%, X7R, AEC-Q200 Grade 1, 0603", Cap_Case=0603, Manufacturer=MuRata, Supplier Part Number 1=490-10673-1-ND, Tempco=X7R, Tolerance_%=10%, Value1=Unknown, Value2=25V, ValueDisplayed=1uF
C23: library part CMP-0007281-4, "CAP, CERM, 680 pF, 100 V, +/- 5%, C0G/NP0, 0603", Cap_Case=0603, Manufacturer=MuRata, Supplier Part Number 1=490-3280-1-ND, Tempco=C0G/NP0, Tolerance_%=5%, Value1=Unknown, Value2=100V, ValueDisplayed=680pF
C24: library part CMP-0007976-2, "CAP, CERM, 1 uF, 50 V, +/- 10%, X7R, AEC-Q200 Grade 1, 0805", Cap_Case=0805, Manufacturer=TDK, Supplier Part Number 1=445-6961-1-ND, Tempco=X7R, Tolerance_%=10%, Value1="0.008782 ohm", Value2=50V, ValueDisplayed=1uF
C25: library part CMP-0006316-1, "CAP, CERM, 220 pF, 50 V, +/- 10%, X7R, AEC-Q200 Grade 1, 0402", Cap_Case=0402, Manufacturer=TDK, Supplier Part Number 1=445-6886-1-ND, Tempco=X7R, Tolerance_%=10%, Value1="9.829 ohm", Value2=50V, ValueDisplayed=220pF
C26: library part CMP-0007131-4, "CAP, CERM, 1000 pF, 100 V, +/- 5%, C0G/NP0, AEC-Q200 Grade 1, 0603", Cap_Case=0603, Manufacturer=MuRata, Supplier Part Number 1=490-4772-1-ND, Tempco=C0G/NP0, Tolerance_%=5%, Value1=Unknown, Value2=100V, ValueDisplayed=1000pF
C27 C30: library part CMP-0006354-2, "CAP, CERM, 1000 pF, 50 V, +/- 10%, X7R, AEC-Q200 Grade 1, 0402", Cap_Case=0402, Manufacturer=MuRata, Supplier Part Number 1=490-4761-1-ND, Tempco=X7R, Tolerance_%=10%, Value1=Unknown, Value2=50V, ValueDisplayed=1000pF
C28: library part CMP-0080702-1, "CAP, CERM, 0.1 µF, 16 V,+/- 5%, X7R, AEC-Q200 Grade 1, 0402", Cap_Case=0402, Manufacturer=MuRata, Supplier Part Number 1=490-16433-1-ND, Tempco=X7R, Tolerance_%=5%, Value2=16V, ValueDisplayed=0.1µF
C31: library part CMP-0006331-2, "CAP, CERM, 0.068 uF, 50 V, +/- 10%, X7R, AEC-Q200 Grade 1, 0402", Cap_Case=0402, Manufacturer=TDK, Supplier Part Number 1=445-6898-1-ND, Tempco=X7R, Tolerance_%=10%, Value1="0.05606 ohm", Value2=50V, ValueDisplayed=0.068uF
C32: library part CMP-0077187-1, "CAP, CERM, 3300 pF, 2000 V,+/- 10%, R, 7x5mm", Cap_Case=7x5x11mm, Manufacturer=TDK, Supplier Part Number 1=445-16022-ND, Tempco=R, Tolerance_%=10%, Value2=2000V, ValueDisplayed=3300pF
C34: library part CMP-0008022-1, "CAP, CERM, 0.47 uF, 50 V, +/- 10%, X7R, AEC-Q200 Grade 1, 0805", Cap_Case=0805, Manufacturer=MuRata, Supplier Part Number 1=490-4788-1-ND, Tempco=X7R, Tolerance_%=10%, Value1=Unknown, Value2=50V, ValueDisplayed=0.47uF
C35: library part CMP-0076706-1, "CAP, CERM, 4.7 µF, 25 V,+/- 10%, X7R, AEC-Q200 Grade 1, 0805", Cap_Case=2x1.25x1.25mm, Manufacturer=TDK, Supplier Part Number 1=445-6967-1-ND, Tempco=X7R, Tolerance_%=10%, Value2=25V, ValueDisplayed=4.7µF
C36 C37: library part CMP-0006308-1, "CAP, CERM, 100 pF, 50 V, +/- 5%, C0G/NP0, AEC-Q200 Grade 1, 0402", Cap_Case=0402, Manufacturer=TDK, Supplier Part Number 1=445-5596-1-ND, Tempco=C0G/NP0, Tolerance_%=5%, Value1=Unknown, Value2=50V, ValueDisplayed=100pF
D1: library part CMP-0065107-4, "Diode, Zener, 200 V, 800 mW, AEC-Q101, DO-219AB", Manufacturer=Vishay-Semiconductor, Power_W=800mW, Value1=0.8W
D2: library part CMP-0029162-1, "Diode, Ultrafast, 600 V, 1 A, AEC-Q101, SMAF", Manufacturer="Fairchild Semiconductor", Supplier Part Number 1=ES1JAFCT-ND, Value1=1A, Value2=1.7V
D3 D8: library part CMP-0028782-1, "Diode, Schottky, 100 V, 1 A, AEC-Q101, SOD-123W", Manufacturer=Nexperia, Supplier Part Number 1=568-12693-1-ND, Value1=1A, Value2=0.77V
D4: library part CMP-0082147-1, "Diode, Ultrafast, 200 V, 1 A, AEC-Q101, SMA", Manufacturer=Vishay-Semiconductor, Supplier Part Number 1=ES1D-E3/61TGICT-ND, Value1=1A, Value2=0.92V
D6: library part CMP-0028754-1, "Diode, Schottky, 100 V, 3 A, AEC-Q101, PowerDI5", Manufacturer="Diodes Inc.", Supplier Part Number 1=PDS3100Q-13DICT-ND, Value1=3A, Value2=0.76V
D7: library part CMP-0084402-1, "Diode, Zener, 18 V, 500 mW, AEC-Q101, SOD-123", Manufacturer="Diodes Inc.", Power_W=500mW, Value1=0.5W
D9 D11 D12: library part CMP-0081199-2, "Diode, Schottky, 30 V, 0.1 A, AEC-Q101, SOD-323", Manufacturer="Diodes Inc.", Value1=0.1A, Value2=1V
D10: library part CMP-0084320-2, "Diode, Superfast Rectifier, 200 V, 1 A, AEC-Q101, 2.8x1.8mm", Manufacturer="Fairchild Semiconductor", Value1=1A, Value2=0.95V
FID1 FID2 FID3: library part CMP-0077181-1, "Fiducial mark.  There is nothing to buy or mount.", Manufacturer=N/A
H1 H2 H3 H4: library part CMP-0003617-1, "Machine Screw, Round, #4-40 x 1/4, Nylon, Philips panhead", Manufacturer="B&F Fastener Supply", Supplier Part Number 1=H542-ND
H5 H6 H7 H8: library part CMP-0003610-1, "Standoff, Hex, 0.5\"L #4-40 Nylon", Manufacturer=Keystone, Supplier Part Number 1=36-1902C-ND
J1 J2 J3: library part CMP-0055551-1, "Header (Shrouded), 5.08mm, 2x1, Tin, R/A, TH", Color=Green, Current_A=12A, Manufacturer="Phoenix Contact", Supplier Part Number 1=277-1095-ND, Voltage_V=400V
J4: library part CMP-0054594-1, "Header, 2.54mm, 1x2, Tin, Black, TH", Color=Black, Current_A=3A, Manufacturer="Sullins Connector Solutions", Supplier Part Number 1=S2012E-01-ND, Voltage_V=1.8kV
L1: library part CMP-0061004-2, "Inductor, Shielded, Composite, 4.7 µH, 5.9 A, 0.04 ohm, AEC-Q200 Grade 1, SMD", Manufacturer=Coilcraft, Value1="0.04 ohm", Value2=5.9A, ValueDisplayed=4.7uH
L2 L5: library part CMP-0003152-1, "Ferrite Bead, 100 ohm @ 100 MHz, 8 A, 1812", Manufacturer="Wurth Elektronik", Supplier Part Number 1=732-3431-1-ND, Value1="0.006 ohm", Value2=8A, ValueDisplayed=DNP
L3: library part CMP-0003152-1, "Ferrite Bead, 100 ohm @ 100 MHz, 8 A, 1812", Manufacturer="Wurth Elektronik", Supplier Part Number 1=732-3431-1-ND, Value1="0.006 ohm", Value2=8A, ValueDisplayed="100 ohm"
L4: library part CMP-0013118-2, "Coupled inductor, 8 A, 0.006 ohm, SMD", Manufacturer=TDK, Supplier Part Number 1=445-2212-1-ND
LBL1: library part CMP-0003625-1, "Thermal Transfer Printable Labels, 0.650\" W x 0.200\" H - 10,000 per roll", Manufacturer=Brady, Supplier Part Number 1=97C5133
Logo1: library part CMP-0074838-1, "Texas Instrument Corporate Signature"
Logo2: library part CMP-0074844-1
Logo3: library part CMP-0074847-1, "FCC_disclaimer"
Logo4: library part CMP-0074769-1
Q1: library part CMP-0750168-1, "MOSFET, N-CH, 60 V, 17 A, AEC-Q101, SO-8FL", Alternate Manufacturer=None, Manufacturer="ON Semiconductor", Value1="0.0088 ohm", Value2="20 nC"
Q2: library part CMP-0000325-2, "Transistor, PNP, 40 V, 0.2 A, SOT-23", Manufacturer="Fairchild Semiconductor", Supplier Part Number 1=MMBT3906FSCT-ND, Value1="0.2 A", Value2=300
Q3 Q4: library part CMP-0085316-1, "MOSFET, N-CH, 200 V, 13 A, AEC-Q101, PowerPAK_SO-8L", Alternate Manufacturer=None, Manufacturer=Vishay-Siliconix, Value1="0.15 ohm", Value2="56 nC"
R1: library part CMP-0020811-2, "RES, 1.0, 5%, 0.125 W, 0805", Manufacturer="Yageo America", Power_W=125mW, Supplier Part Number 1=311-1.0ARCT-ND, Tempco="200 ppm/C", Tolerance_%=5%, Value2=0.125W, Value_Code=1R00, ValueDisplayed=1.0
R2 R3: library part CMP-0018701-3, "RES, 56 k, 5%, 0.25 W, AEC-Q200 Grade 0, 1206", Manufacturer=Vishay-Dale, Power_W=250mW, Supplier Part Number 1=541-56KECT-ND, Tempco="200 ppm/C", Tolerance_%=5%, Value2=0.25W, Value_Code=56k0, ValueDisplayed=56k
R4: library part CMP-0018578-3, "RES, 10, 5%, 0.25 W, AEC-Q200 Grade 0, 1206", Manufacturer=Vishay-Dale, Power_W=250mW, Supplier Part Number 1=541-10ECT-ND, Tempco="200 ppm/C", Tolerance_%=5%, Value2=0.25W, Value_Code=10R0, ValueDisplayed=10
R5 R7: library part CMP-0018655-3, "RES, 30, 5%, 0.25 W, AEC-Q200 Grade 0, 1206", Manufacturer=Vishay-Dale, Power_W=250mW, Supplier Part Number 1=541-30ECT-ND, Tempco="200 ppm/C", Tolerance_%=5%, Value2=0.25W, Value_Code=30R0, ValueDisplayed=30
R6 R9: library part CMP-0022003-4, "RES, 10.0, 1%, 0.1 W, AEC-Q200 Grade 0, 0603", Manufacturer=Vishay-Dale, Power_W=100mW, Supplier Part Number 1=541-10.0HCT-ND, Tempco="100 ppm/C", Tolerance_%=1%, Value2=0.1W, Value_Code=10R0, ValueDisplayed=10.0
R8: library part CMP-0026502-2, "RES, 66.5 k, 1%, 0.063 W, AEC-Q200 Grade 0, 0402", Manufacturer=Vishay-Dale, Power_W=63mW, Supplier Part Number 1=541-66.5KLCT-ND, Tempco="100 ppm/C", Tolerance_%=1%, Value2=0.063W, Value_Code=66k5, ValueDisplayed=66.5k
R10: library part CMP-0018627-3, "RES, 20, 5%, 0.25 W, AEC-Q200 Grade 0, 1206", Manufacturer=Vishay-Dale, Power_W=250mW, Supplier Part Number 1=541-20ECT-ND, Tempco="200 ppm/C", Tolerance_%=5%, Value2=0.25W, Value_Code=20R0, ValueDisplayed=20
R11: library part CMP-0025697-4, "RES, 0, 5%, 0.1 W, AEC-Q200 Grade 0, 0603", Manufacturer=Vishay-Dale, Power_W=100mW, Supplier Part Number 1=541-0.0GCT-ND, Tempco="200 ppm/C", Tolerance_%=5%, Value2=0.1W, Value_Code=0000, ValueDisplayed=0
R12: library part CMP-0026028-3, "RES, 15.4 k, 1%, 0.063 W, AEC-Q200 Grade 0, 0402", Manufacturer=Vishay-Dale, Power_W=63mW, Supplier Part Number 1=541-15.4KLCT-ND, Tempco="100 ppm/C", Tolerance_%=1%, Value2=0.063W, Value_Code=15k4, ValueDisplayed=15.4k
R13: library part CMP-0026823-3, "RES, 100 k, 5%, 0.063 W, AEC-Q200 Grade 0, 0402", Manufacturer=Vishay-Dale, Power_W=63mW, Supplier Part Number 1=541-100KJCT-ND, Tempco="200 ppm/C", Tolerance_%=5%, Value2=0.063W, Value_Code=100k
R14 R21: library part CMP-0078193-1, "RES, 1.0 k, 5%, 0.1 W, AEC-Q200 Grade 0, 0402", Manufacturer=Panasonic, Power_W=100mW, Supplier Part Number 1=P1.0KJCT-ND, Tempco="200 ppm/C", Tolerance_%=5%, Value2=0.1W, Value_Code=1k00, ValueDisplayed=1.0k
R15 R16: library part CMP-0025951-3, "RES, 100, 1%, 0.063 W, AEC-Q200 Grade 0, 0402", Manufacturer=Vishay-Dale, Power_W=63mW, Supplier Part Number 1=541-100LCT-ND, Tempco="100 ppm/C", Tolerance_%=1%, Value2=0.063W, Value_Code=100R, ValueDisplayed=100
R17 R18: library part CMP-0017834-1, "RES, 0.007, 1%, 1 W, AEC-Q200 Grade 0, 1206", Manufacturer="Yageo America", Power_W=1W, Supplier Part Number 1=PE1206FRF470R007L-ND, Tempco="100 ppm/C", Tolerance_%=1%, Value_Code=7L000, ValueDisplayed=0.007
R19: library part CMP-0026340-1, "RES, 3.92 k, 1%, 0.063 W, 0402", Manufacturer=Vishay-Dale, Power_W=63mW, Supplier Part Number 1=541-3.92KLCT-ND, Tempco="100 ppm/C", Tolerance_%=1%, Value2=0.063W, Value_Code=3k92, ValueDisplayed=3.92k
R20 R32: library part CMP-0026822-3, "RES, 0, 5%, 0.063 W, AEC-Q200 Grade 0, 0402", Manufacturer=Vishay-Dale, Power_W=63mW, Supplier Part Number 1=541-0.0JCT-ND, Tempco="200 ppm/C", Tolerance_%=5%, Value2=0.063W, Value_Code=0000, ValueDisplayed=0
R22: library part CMP-0026892-5, "RES, 2.7 k, 5%, 0.063 W, AEC-Q200 Grade 0, 0402", Manufacturer=Vishay-Dale, Power_W=63mW, Supplier Part Number 1=541-2.7KJCT-ND, Tempco="200 ppm/C", Tolerance_%=5%, Value2=0.063W, Value_Code=2k70, ValueDisplayed=2.7k
R23 R26 R29: library part CMP-0022004-4, "RES, 10.0, 1%, 0.25 W, AEC-Q200 Grade 0, 0603", Manufacturer=Vishay-Dale, Power_W=250mW, Supplier Part Number 1=541-10.0SCT-ND, Tempco="100 ppm/C", Tolerance_%=1%, Value2=0.25W, Value_Code=10R0, ValueDisplayed=10.0
R24: library part CMP-0025805-4, "RES, 3.3, 5%, 0.1 W, AEC-Q200 Grade 0, 0603", Manufacturer=Vishay-Dale, Power_W=100mW, Supplier Part Number 1=541-3.3GCT-ND, Tempco="200 ppm/C", Tolerance_%=5%, Value2=0.1W, Value_Code=3R30, ValueDisplayed=3.3
R25 R30: library part CMP-0026754-1, "RES, 10.0 k, 1%, 0.063 W, AEC-Q200 Grade 0, 0402", Manufacturer="Stackpole Electronics Inc", Power_W=63mW, Supplier Part Number 1=RMCF0402FT10K0CT-ND, Tempco="100 ppm/C", Tolerance_%=1%, Value2=0.063W, Value_Code=10k0, ValueDisplayed=10.0k
R27 R28: library part CMP-0025963-3, "RES, 10.0, 1%, 0.063 W, AEC-Q200 Grade 0, 0402", Manufacturer=Vishay-Dale, Power_W=63mW, Supplier Part Number 1=541-10.0LCT-ND, Tempco="100 ppm/C", Tolerance_%=1%, Value2=0.063W, Value_Code=10R0, ValueDisplayed=10.0
R31 R34: library part CMP-0018186-1, "RES, 300, 1%, 0.25 W, 1206", Manufacturer="Yageo America", Power_W=250mW, Supplier Part Number 1=311-300FRCT-ND, Tempco="100 ppm/C", Tolerance_%=1%, Value2=0.25W, Value_Code=300R, ValueDisplayed=300
R33: library part CMP-0026535-2, "RES, 71.5 k, 1%, 0.063 W, AEC-Q200 Grade 0, 0402", Manufacturer=Vishay-Dale, Power_W=63mW, Supplier Part Number 1=541-71.5KLCT-ND, Tempco="100 ppm/C", Tolerance_%=1%, Value2=0.063W, Value_Code=71k5, ValueDisplayed=71.5k
R35: library part CMP-0018797-2, "RES, 1.00 k, 0.1%, 0.25 W, 1206", Manufacturer="TE Connectivity", Power_W=250mW, Supplier Part Number 1=A105676-ND, Tempco="15 ppm/C", Tolerance_%=0.1%, Value2=0.25W, Value_Code=1k00, ValueDisplayed=1.00k
R36: library part CMP-0018797-2, "RES, 1.00 k, 0.1%, 0.25 W, 1206", Manufacturer="TE Connectivity", Power_W=250mW, Supplier Part Number 1=A105676-ND, Tempco="15 ppm/C", Tolerance_%=0.1%, Value2=0.25W, Value_Code=1k00, ValueDisplayed=DNP
R37 R38: library part CMP-0016775-3, "RES, 200 k, 1%, 0.25 W, AEC-Q200 Grade 0, 1206", Manufacturer=Vishay-Dale, Power_W=250mW, Supplier Part Number 1=541-200KFCT-ND, Tempco="100 ppm/C", Tolerance_%=1%, Value2=0.25W, Value_Code=200k
T1: library part CMP-0091232-2, "EFD20 12PIN SMD FLYBACK TRANSFORMER", Frequency_Fixed=100kHz, Manufacturer=Coilcraft, Operating Temperature Range=to, Voltage_Isolation_Vrms=3000Vrms
TP1 TP2 TP3: library part CMP-0055152-1, "Test Point, Miniature, SMT", Manufacturer=Keystone, Supplier Part Number 1=36-5015TR-ND
U1: library part CMP-0088384-2, "2.2-MHz Wide VIN 65-V Non-synchronous Boost/SEPIC/Flyback Controller with Dual Random Spread Spectrum", Manufacturer="Texas Instruments", Max Supply Voltage=60V, Min Supply Voltage=1.5V, Nominal Supply Current=490uA, Operating Temperature Range="-40°C to +150°C", Switching Frequency=100-2200kHz
U2: library part CMP-0065057-2, "620-V High-Side Low-Side Gate Driver with 2.5A Peak Output and RobustDrive, D0008A (SOIC-8)", Alternate Manufacturer="Texas Instruments"
ZZ1: library part CMP-0003616-3
ZZ2: library part CMP-0077236-1
ZZ3: library part CMP-0077237-1
ZZ4: library part CMP-0077238-1

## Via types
v1: diameter 0.9, hole 0.5, Top Layer to Bottom Layer, 133 vias
v2: diameter 0.6, hole 0.3, Top Layer to Bottom Layer, 56 vias
v3: diameter 0.5, hole 0.2, Top Layer to Bottom Layer, 3 vias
